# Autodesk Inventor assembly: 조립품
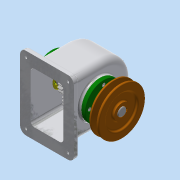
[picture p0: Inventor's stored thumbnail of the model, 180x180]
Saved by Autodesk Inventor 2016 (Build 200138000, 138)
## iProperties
Created: 2018-11
Part Number: 조립품
Material: 일반
Document SubType Name: Assembly
Designer: user
Author: user
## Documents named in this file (14)
- C:\Users\user\Desktop\481111V1006\조립품.iam
- C:\Users\user\Desktop\481111V1006\V-벨트풀리.ipt
- C:\Users\user\Desktop\481111V1006\뒤커버.ipt
- C:\Users\user\Desktop\481111V1006\멈춤나사 M4.ipt
- C:\Users\user\Desktop\481111V1006\베어링 6203.ipt
- C:\Users\user\Desktop\481111V1006\본체.ipt
- C:\Users\user\Desktop\481111V1006\볼트 M4.ipt
- C:\Users\user\Desktop\481111V1006\부시.ipt
- C:\Users\user\Desktop\481111V1006\스퍼기어.ipt
- C:\Users\user\Desktop\481111V1006\앞커버.ipt
- C:\Users\user\Desktop\481111V1006\오일 실 28 40 8.ipt
- C:\Users\user\Desktop\481111V1006\축.ipt
- C:\Users\user\Desktop\481111V1006\키 5x5x18.ipt
- C:\Users\user\Desktop\481111V1006\키 6x6x22.ipt
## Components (1 placed, 1 different names)
1. V-벨트풀리:1
